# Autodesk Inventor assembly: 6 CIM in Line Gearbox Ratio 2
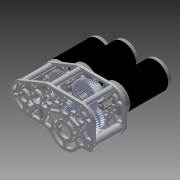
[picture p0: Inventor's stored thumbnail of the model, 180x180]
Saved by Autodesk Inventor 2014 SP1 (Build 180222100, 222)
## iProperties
Created: 2014-11
Part Number: 6 CIM in Line Gearbox Ratio 2
Document SubType Name: Assembly
Designer: Michael
Mass: 4438.01 g
Surface Area: 2514.13 cm^2
Volume: 1336.24 cm^3
Density: 3.32126 g/cm^3
Author: Michael
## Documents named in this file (14)
- C:\Users\Michael\Documents\Inventor\6 CIM in Line\6 CIM in Line Gearbox Ratio 2.iam
- C:\Users\Michael\Documents\Inventor\6 CIM in Line\Gearbox Plate Ratio 2.ipt
- C:\Users\Michael\Documents\Inventor\Bicycle\Imported Components\40T .5 inch\40T .5 inch.ipt
- C:\Users\Michael\Documents\Inventor\Bicycle\Imported Components\11t\11t.ipt
- C:\Users\Michael\Documents\Inventor\Bicycle\Imported Components\50t\50t.ipt
- C:\Users\Michael\Documents\Inventor\Bicycle\Imported Components\36t\36t.ipt
- C:\Users\Michael\Documents\Inventor\6 CIM V2\6 CIM Gearbox V2\217-2000 CIM motor.ipt
- C:\Users\Michael\Documents\Inventor\Bicycle\Imported Components\User Library-16T Gear AndyMark am-0747\User Library-16T Gear AndyMark am-0747.ipt
- C:\Users\Michael\Documents\Inventor\Bicycle\Imported Components\40tDogGear\40tDogGear.ipt
- C:\Users\Michael\Documents\Inventor\Bicycle\Imported Components\60tDogGear\60tDogGear.ipt
- C:\Users\Michael\Documents\Inventor\6 CIM in Line\Piston Mount in Line.ipt
- C:\Users\Michael\Documents\Inventor\6 CIM in Line\Gearbox Plate Ratio 2 MIR.ipt
- C:\Users\Michael\Documents\Inventor\6 CIM V2\6 CIM Gearbox V2\Standoff.ipt
- C:\Users\Michael\Documents\Inventor\6 CIM V2\6 CIM Gearbox V2\Big Standoff.ipt
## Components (20 placed, 13 different names)
1. Gearbox Plate Ratio 2:1 — Mate:1, Mate:2, Mate:3, Mate:5, Mate:7, Mate:8, Mate:12, Mate:13, Mate:14, Mate:15, Mate:16, Mate:17, Mate:18, Mate:19, Mate:20, Mate:21, Mate:25, Mate:26, Angle:3, Mate:28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
2. 40T .5 inch:1 — Mate:2, Mate:10, Rotation:5, Rotation:6
3. 11t:1 — Mate:1, Mate:3, Mate:10, Flush:1, Rotation:5
4. 11t:2 — Mate:5, Flush:1, Flush:2, Rotation:6, Rotation:7
5. 50t:1 — Mate:7, Rotation:4, Mate:11, Angle:1, Mate:22, Rotation:7, Mate:23, Mate:24, Angle:2, Mate:27
6. 11t:3 — Mate:8, Rotation:4, Flush:2
7. 36t:1 — Mate:11, Angle:1, Mate:21, Mate:22, Rotation:8, Flush:3
8. 217-2000 CIM motor:1 — Mate:13, Mate:15, Mate:18
9. 217-2000 CIM motor:2 — Mate:14, Mate:16, Mate:19
10. 217-2000 CIM motor:3 — Mate:12, Mate:17, Mate:20
11. User Library-16T Gear AndyMark am-0747:1 — Mate:23, Mate:24, Angle:2, Rotation:9
12. 40tDogGear:1 — Mate:25, Rotation:8, Flush:3
13. 60tDogGear:1 — Mate:26, Angle:3, Mate:27, Rotation:9
14. Piston Mount in Line:1 — Mate:28, Mate:29
15. Gearbox Plate Ratio 2 MIR:1 — Mate:30, Mate:31, Mate:32, Mate:36, Mate:37, Mate:38
16. Standoff:1 — Mate:35, Mate:36
17. Big Standoff:1 — Mate:33, Mate:34
18. Standoff:2 — Mate:41, Mate:42
19. Standoff:3 — Mate:39, Mate:40
20. Big Standoff:2 — Mate:37, Mate:38
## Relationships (51: Mate 39, RelateRotation 6, Angle 3, Flush 3)
- Mate:1: Gearbox Plate Ratio 2:1 ↔ 11t:1
- Mate:2: Gearbox Plate Ratio 2:1 ↔ 40T .5 inch:1
- Mate:3: Gearbox Plate Ratio 2:1 ↔ 11t:1
- Mate:5: Gearbox Plate Ratio 2:1 ↔ 11t:2
- Mate:7: Gearbox Plate Ratio 2:1 ↔ 50t:1
- Mate:8: Gearbox Plate Ratio 2:1 ↔ 11t:3
- Mate:10: 40T .5 inch:1 ↔ 11t:1
- Rotation:4 [RelateRotation]: 50t:1 ↔ 11t:3
- Mate:11: 50t:1 ↔ 36t:1
- Angle:1: 50t:1 ↔ 36t:1
- Mate:12: Gearbox Plate Ratio 2:1 ↔ 217-2000 CIM motor:3
- Mate:13: Gearbox Plate Ratio 2:1 ↔ 217-2000 CIM motor:1
- Mate:14: Gearbox Plate Ratio 2:1 ↔ 217-2000 CIM motor:2
- Mate:15: Gearbox Plate Ratio 2:1 ↔ 217-2000 CIM motor:1
- Mate:16: Gearbox Plate Ratio 2:1 ↔ 217-2000 CIM motor:2
- Mate:17: Gearbox Plate Ratio 2:1 ↔ 217-2000 CIM motor:3
- Mate:18: Gearbox Plate Ratio 2:1 ↔ 217-2000 CIM motor:1
- Mate:19: Gearbox Plate Ratio 2:1 ↔ 217-2000 CIM motor:2
- Mate:20: Gearbox Plate Ratio 2:1 ↔ 217-2000 CIM motor:3
- Mate:21: Gearbox Plate Ratio 2:1 ↔ 36t:1
- Flush:1: 11t:1 ↔ 11t:2
- Flush:2: 11t:2 ↔ 11t:3
- Mate:22: 50t:1 ↔ 36t:1
- Rotation:5 [RelateRotation]: 40T .5 inch:1 ↔ 11t:1
- Rotation:6 [RelateRotation]: 40T .5 inch:1 ↔ 11t:2
- Rotation:7 [RelateRotation]: 11t:2 ↔ 50t:1
- Mate:23: 50t:1 ↔ User Library-16T Gear AndyMark am-0747:1
- Mate:24: 50t:1 ↔ User Library-16T Gear AndyMark am-0747:1
- Angle:2: 50t:1 ↔ User Library-16T Gear AndyMark am-0747:1
- Mate:25: Gearbox Plate Ratio 2:1 ↔ 40tDogGear:1
- Mate:26: Gearbox Plate Ratio 2:1 ↔ 60tDogGear:1
- Angle:3: Gearbox Plate Ratio 2:1 ↔ 60tDogGear:1
- Rotation:8 [RelateRotation]: 36t:1 ↔ 40tDogGear:1
- Mate:27: 50t:1 ↔ 60tDogGear:1
- Flush:3: 36t:1 ↔ 40tDogGear:1
- Mate:28: Gearbox Plate Ratio 2:1 ↔ Piston Mount in Line:1
- Mate:29: Gearbox Plate Ratio 2:1 ↔ Piston Mount in Line:1
- Rotation:9 [RelateRotation]: User Library-16T Gear AndyMark am-0747:1 ↔ 60tDogGear:1
- Mate:30: Gearbox Plate Ratio 2:1 ↔ Gearbox Plate Ratio 2 MIR:1
- Mate:31: Gearbox Plate Ratio 2:1 ↔ Gearbox Plate Ratio 2 MIR:1
- Mate:32: Gearbox Plate Ratio 2:1 ↔ Gearbox Plate Ratio 2 MIR:1
- Mate:33: Gearbox Plate Ratio 2:1 ↔ Big Standoff:1
- Mate:34: Gearbox Plate Ratio 2:1 ↔ Big Standoff:1
- Mate:35: Gearbox Plate Ratio 2:1 ↔ Standoff:1
- Mate:36: Gearbox Plate Ratio 2 MIR:1 ↔ Standoff:1
- Mate:37: Gearbox Plate Ratio 2 MIR:1 ↔ Big Standoff:2
- Mate:38: Gearbox Plate Ratio 2 MIR:1 ↔ Big Standoff:2
- Mate:39: Gearbox Plate Ratio 2:1 ↔ Standoff:3
- Mate:40: Gearbox Plate Ratio 2:1 ↔ Standoff:3
- Mate:41: Gearbox Plate Ratio 2:1 ↔ Standoff:2
- Mate:42: Gearbox Plate Ratio 2:1 ↔ Standoff:2
